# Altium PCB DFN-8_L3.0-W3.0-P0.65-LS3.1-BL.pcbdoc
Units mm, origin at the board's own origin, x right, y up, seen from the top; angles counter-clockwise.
Board outline 15.82 x 16.43 mm, 2 copper layers (Top Layer, Bottom Layer), stack 0 mm thick; 1 components, 0 nets, 9 pads, 0 vias.
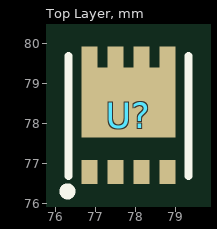
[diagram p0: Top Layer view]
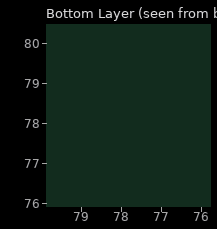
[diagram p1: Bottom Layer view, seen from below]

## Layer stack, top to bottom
Top Layer: signal copper (thickness not stored)
Bottom Layer: signal copper (thickness not stored)

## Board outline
85.674,69.85 69.85,69.85 69.85,86.275 85.674,86.275

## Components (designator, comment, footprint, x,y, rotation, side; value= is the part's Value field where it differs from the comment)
U? "" DFN-8_L3.0-W3.0-P0.65-LS3.1-BL 77.824,78.205 r0 top

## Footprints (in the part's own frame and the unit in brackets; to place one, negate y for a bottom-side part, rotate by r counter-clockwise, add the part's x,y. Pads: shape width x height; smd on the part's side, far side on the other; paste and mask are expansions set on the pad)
DFN-8_L3.0-W3.0-P0.65-LS3.1-BL [mm]
  rect 0.4x0.6 smd paste-100 mask+0.051: 1(-0.975,-1.42) 2(-0.325,-1.419) 3(0.325,-1.419) 4(0.975,-1.419) 5(-0.975,1.42) 5(-0.325,1.42) 5(0.325,1.42) 5(0.975,1.42)
  rect 2.35x1.75 smd paste-100 mask+0.051: 5(0,0.315)
  silkscreen extent -1.62,-2.01 1.5,1.48

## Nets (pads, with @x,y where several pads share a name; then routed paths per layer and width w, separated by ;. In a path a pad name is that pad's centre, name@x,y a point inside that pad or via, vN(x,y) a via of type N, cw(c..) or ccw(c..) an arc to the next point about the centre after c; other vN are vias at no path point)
pads on no net: U?.1 U?.2 U?.3 U?.4 U?.5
